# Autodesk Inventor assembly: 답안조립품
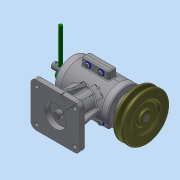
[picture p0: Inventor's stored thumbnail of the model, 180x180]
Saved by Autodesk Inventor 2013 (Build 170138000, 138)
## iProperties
Created: 2015-12
Part Number: 답안조립품
Document SubType Name: Assembly
Designer: Administrator
Author: Administrator
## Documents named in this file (19)
- C:\Users\Administrator\Desktop\351208V1035\답안조립품.iam
- C:\Users\Administrator\Desktop\351208V1035\본체.ipt
- C:\Users\Administrator\Desktop\351208V1035\V-벨트풀리.ipt
- C:\Users\Administrator\Desktop\351208V1035\너트 M4.ipt
- C:\Users\Administrator\Desktop\351208V1035\뒤커버.ipt
- C:\Users\Administrator\Desktop\351208V1035\레바.ipt
- C:\Users\Administrator\Desktop\351208V1035\멈춤나사 M3x8.ipt
- C:\Users\Administrator\Desktop\351208V1035\베어링 6201.ipt
- C:\Users\Administrator\Desktop\351208V1035\베어링 6202.ipt
- C:\Users\Administrator\Desktop\351208V1035\본체커버.ipt
- C:\Users\Administrator\Desktop\351208V1035\볼트 M3x0.5x8.ipt
- C:\Users\Administrator\Desktop\351208V1035\볼트 M4 x 16.ipt
- C:\Users\Administrator\Desktop\351208V1035\스프링 - [가변].ipt
- C:\Users\Administrator\Desktop\351208V1035\슬라이드.ipt
- C:\Users\Administrator\Desktop\351208V1035\앞커버.ipt
- C:\Users\Administrator\Desktop\351208V1035\오일실 12 22 7.ipt
- C:\Users\Administrator\Desktop\351208V1035\와셔 ST 4-100.ipt
- C:\Users\Administrator\Desktop\351208V1035\키 4 x 4 x 18.ipt
- C:\Users\Administrator\Desktop\351208V1035\편심축.ipt
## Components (13 placed, 4 different names)
1. V-벨트풀리:1 — 플러쉬:1
2. ISO 4032 M4:1
3. ISO 4762 M4 x 16:1
4. ISO 7091 ST 4 - 100 HV:1
5. ISO 4762 M4 x 16:2
6. ISO 4762 M4 x 16:3
7. ISO 4762 M4 x 16:4
8. ISO 7091 ST 4 - 100 HV:2
9. ISO 7091 ST 4 - 100 HV:3
10. ISO 7091 ST 4 - 100 HV:4
11. ISO 4032 M4:2
12. ISO 4032 M4:3
13. ISO 4032 M4:4
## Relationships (1: Flush 1)
- 플러쉬:1 [Flush]: V-벨트풀리:1
